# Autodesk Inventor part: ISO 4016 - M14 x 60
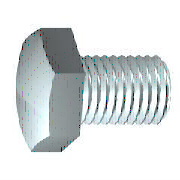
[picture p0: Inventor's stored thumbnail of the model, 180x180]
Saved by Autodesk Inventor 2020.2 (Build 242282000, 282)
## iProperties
Manager: www.cadconsulting.pl
Company: Fabian Stasiak CAD Consulting
Created: 2006-02
Part Number: ISO 4016 - M14 x 60
Material: Stal, miękka
Description: Śruba
Document SubType Name: Modeling
Standard: ISO 4016
Designer: F.Stasiak
Standards Organization: DIN
Language: pl-PL
Size Designation: M14 x 60
Categories: <MemberInstance><Categories><Category DisplayName="Mocowania" InternalName="e4da775c-781d-43d5-af7c-5136215cf5a6" Mnemonic="FSTN"><Category DisplayName="Śruby"
Density: 1 g/cm^3
Appearance: Stal
Author: F.Stasiak
Subject: Zbiór ćwiczeń. Autodesk Inventor 2020. Kurs podstawowy
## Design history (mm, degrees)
sketch "Szkic1"
  geometry: L1 (0, 7)-(60, 7); L2 (60, 7)-(60, 0); L3 (60, 0)-(0, 0); L4 (-6, 0)-(78, 0) reference; L5 (0, -0.7)-(0, 9.1) reference; L6 (0, 7)-(0, 0)
  constraints: 8 end point, 3 point on line, 1 collinear
  dimensions: "d2" = 14 diameter of L1 L3 (= GD); "d59" = 60 distance between parallel lines of L2 L5 (= NLG)
revolve "Bryła" sketch "Szkic1" stored, may be unused: angle "d12" = 90 deg
sketch "Szkic2"
  geometry: L1 (0, 12.124)-(10.5, 6.062); L2 (10.5, 6.062)-(10.5, -6.062); L3 (10.5, -6.062)-(0, -12.124); L4 (0, -12.124)-(-10.5, -6.062); L5 (-10.5, -6.062)-(-10.5, 6.062); L6 (-10.5, 6.062)-(0, 12.124); L7 (-8.4, 0)-(11.2, 0) reference; L8 (0, 11.2)-(0, -8.4) reference; 2 further points
  constraints: 12 end point, 2 point on line, 1 coincident, 1 vertical, 11 other
  dimensions: "d11" = 21 distance between parallel lines of L5 L2 (= SW)
extrude "Głowica" join sketch "Szkic2" distance "d3" = 8.8 (= KOH); taper "d4" = 0 deg
sketch "Szkic4"
  geometry: L1 (-7.588, 12.6)-(-8.8, 10.5); L2 (-1.1, 0)-(-0.234, 0); L3 (-9.657, 0)-(2.336, 0) reference; L4 (-8.8, 12.6)-(-7.588, 12.6); L5 (-8.8, 10.5)-(-8.8, 12.6); L6 (0, 16.38)-(0, -1.26) reference
  constraints: 8 end point, 1 parallel, 1 perpendicular, 1 point on line
  dimensions: "d65" = 21 diameter of L1.end L2 (= SW); "d67" = 30 deg angle of L1 L5 (= ANG1); "d68" = 25.2 diameter of L4 L2 (= 1.2 x SW); "d69" = 8.8 distance between parallel lines of L5 L6 (= KOH)
revolve "Faza1" sketch "Szkic4" stored, may be unused: angle "d21" = 90 deg
workplane "Work Plane1"
node "Bryła1"
node "Korpusy bryłowe"
node "Korpusy powierzchniowe"
feature "Gwint" dims "d15" = 34 (= GEL), "d16" = 0
chamfer "Faza2" distance "d6" = 1.2269 (= -0.5 x SPD + 0.5 x GD); stored, may be unused: second distance "d7" = 1.227 (computed from GUL), angle "d55" = 45 deg
other parameters: "NLG" = 60 [user parameter; used in 1 equation term], "GD" = 14 (= NND) [user parameter; used in 2 equation terms], "BDM" = 14 (= NND) [user parameter], "KOH" = 8.8 [user parameter; used in 2 equation terms], "GEL" = 34 [user parameter; used in 1 equation term], "SW" = 21 [user parameter; used in 5 equation terms], "SW0" = 21 (= SW) [user parameter], "SPD" = 11.5462 (= NND - 1.2269 x PTC) [user parameter; used in 1 equation term], "SD2" = 14 (= NND) [user parameter], "SD" = 0 [user parameter], "ANG1" = 30 deg [user parameter; used in 1 equation term], "GAL" = 1.2269 (= 0.61345 x PTC) [user parameter], "GUL" = 1.2269 (= 0.61345 x PTC) [user parameter; used in 1 equation term], "d8" = 0, "RR" = 0.1 [user parameter], "d58" = 0, "d61" = 0, "TPU" = 5 (computed from PTC) [user parameter], "GD1" = 11.5462 (= THREADDIA - 1.2269 x PTC) [user parameter], "THREADDIA" = 14 [user parameter; used in 1 equation term], "TOA" = 30 deg [user parameter], "PTC" = 2 [user parameter; used in 5 equation terms], "NND" = 14 [user parameter; used in 4 equation terms], "E0" = 24.255 (= 1.155 x SW) [user parameter]
